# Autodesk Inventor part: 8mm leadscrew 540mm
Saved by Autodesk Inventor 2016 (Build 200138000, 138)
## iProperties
Created: 2016-03
Part Number: 8mm leadscrew 540mm
Material: Generic
Document SubType Name: Modeling
Designer: bongo_000
Density: 1 g/cm^3
Appearance: Default
Author: bongo_000
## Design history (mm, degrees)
feature "BOSS-EXTRUDE1"
body "Solid1"
